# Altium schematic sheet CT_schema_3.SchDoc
size 511 x 403 mm
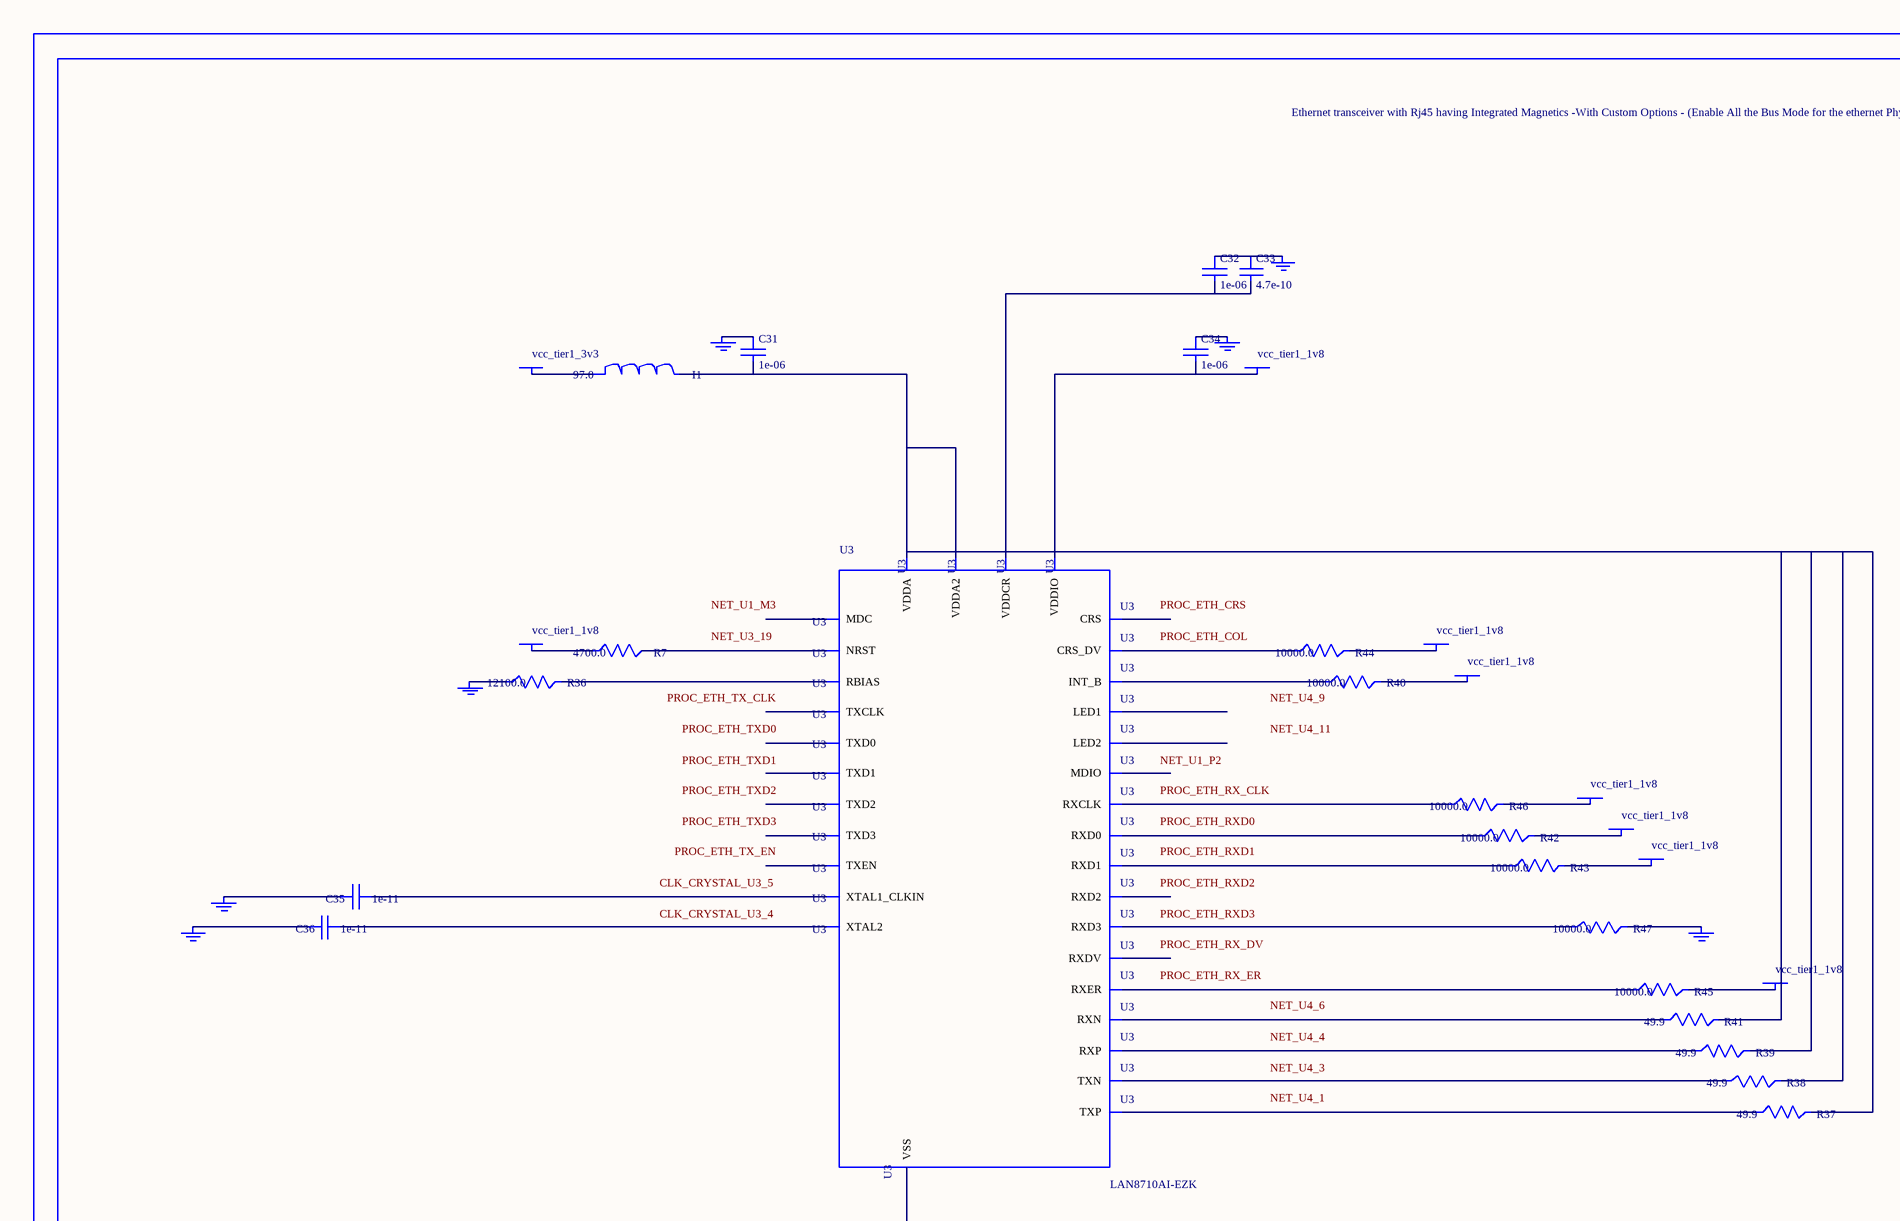
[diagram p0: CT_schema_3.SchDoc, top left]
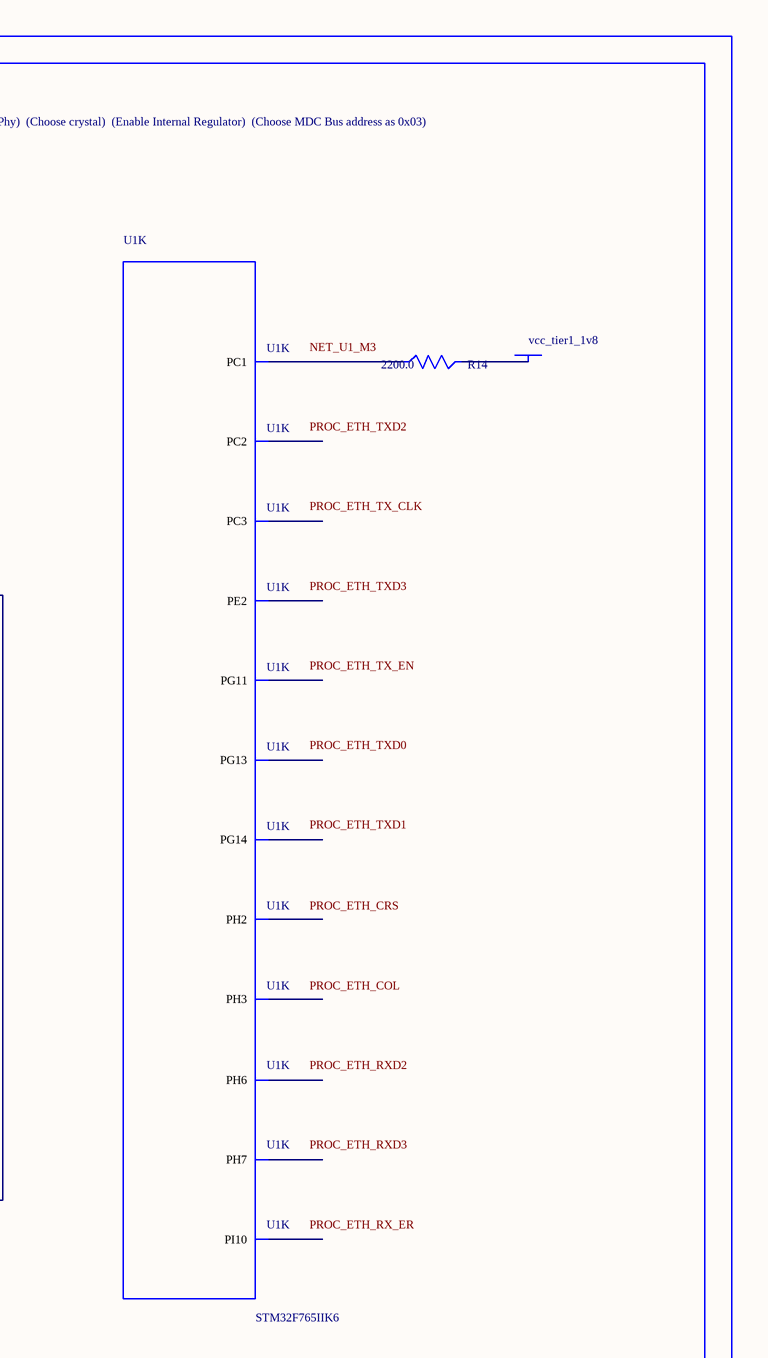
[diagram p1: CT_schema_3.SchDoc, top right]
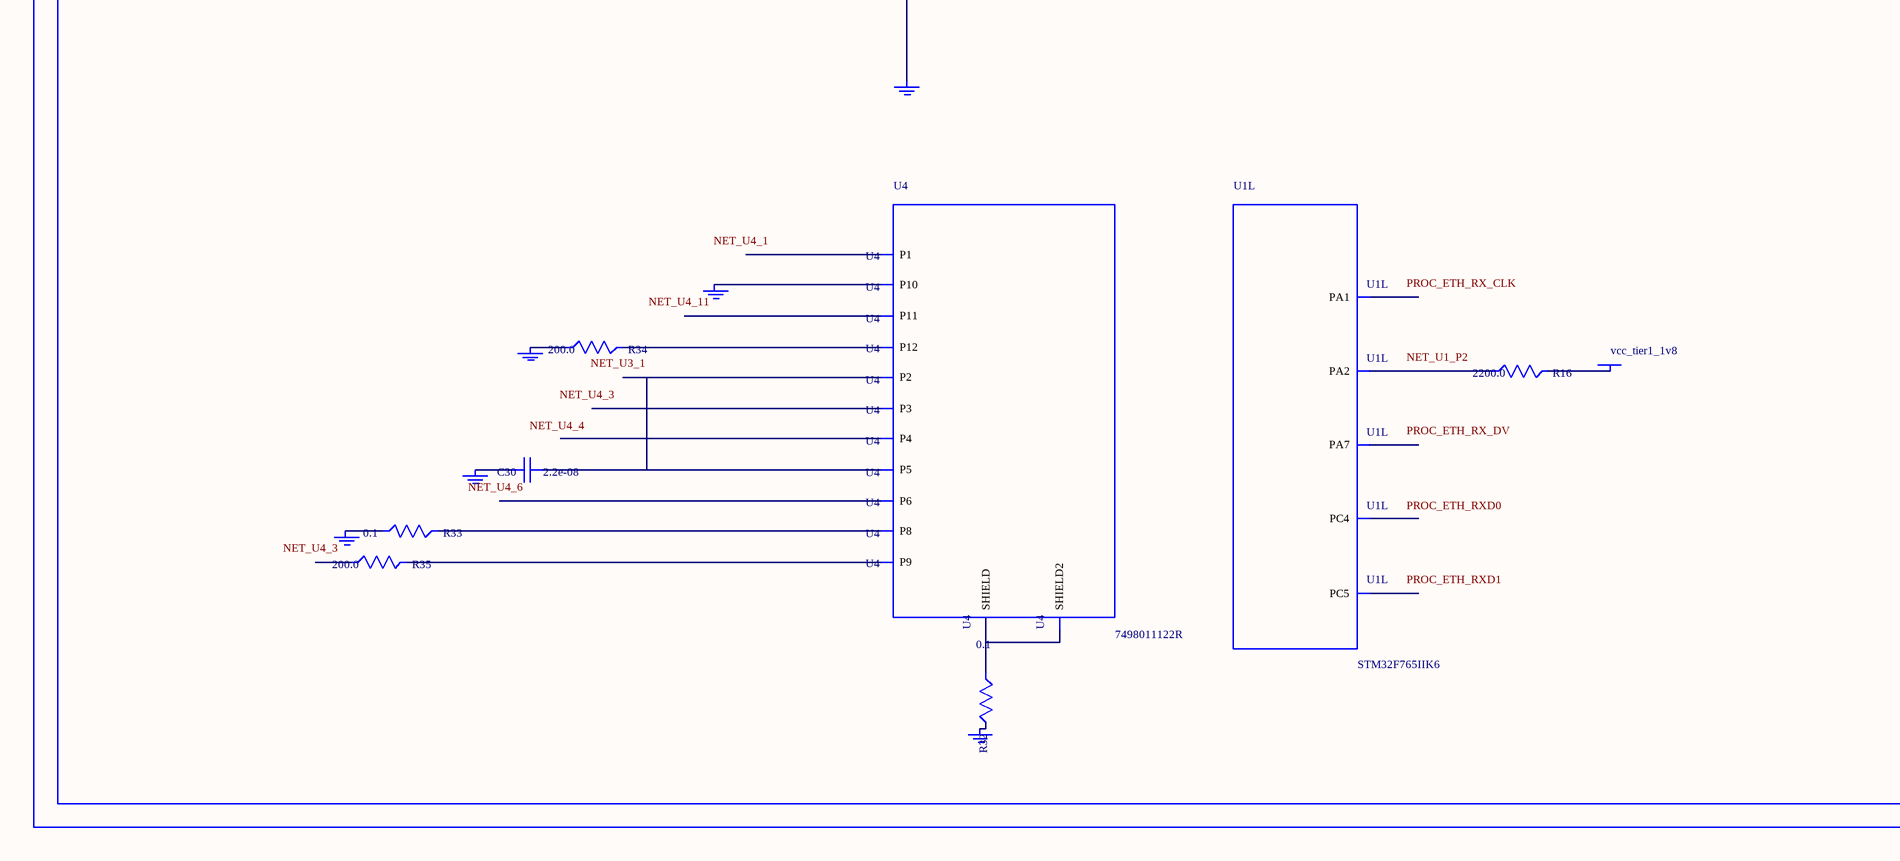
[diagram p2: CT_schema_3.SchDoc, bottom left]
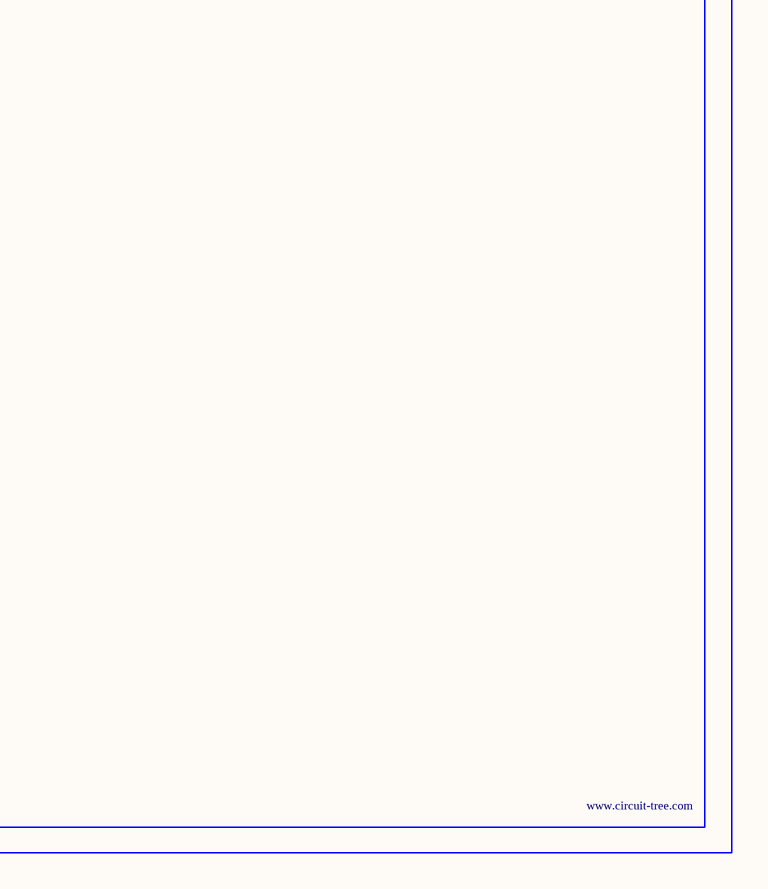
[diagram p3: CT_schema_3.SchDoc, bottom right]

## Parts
BORDER2  (no value)
C30  2.2e-08  [C0402]
C31  1e-06  [C0603]
C32  1e-06  [C0603]
C33  4.7e-10  [C0603]
C34  1e-06  [C0603]
C35  1e-11  [C0402]
C36  1e-11  [C0402]
GND_INSTANCE_2_0  (no value)
GND_INSTANCE_2_1  (no value)
GND_INSTANCE_2_2  (no value)
GND_INSTANCE_2_3  (no value)
GND_INSTANCE_2_4  (no value)
GND_INSTANCE_2_5  (no value)
GND_INSTANCE_2_6  (no value)
GND_INSTANCE_2_7  (no value)
GND_INSTANCE_2_8  (no value)
GND_INSTANCE_2_9  (no value)
GND_INSTANCE_2_10  (no value)
GND_INSTANCE_2_11  (no value)
GND_INSTANCE_2_12  (no value)
I1  97.0  [R0603]
POWER_INSTANCE_2_0  vcc_tier1_3v3
POWER_INSTANCE_2_1  vcc_tier1_1v8
POWER_INSTANCE_2_2  vcc_tier1_1v8
POWER_INSTANCE_2_3  vcc_tier1_1v8
POWER_INSTANCE_2_4  vcc_tier1_1v8
POWER_INSTANCE_2_5  vcc_tier1_1v8
POWER_INSTANCE_2_6  vcc_tier1_1v8
POWER_INSTANCE_2_7  vcc_tier1_1v8
POWER_INSTANCE_2_8  vcc_tier1_1v8
POWER_INSTANCE_2_9  vcc_tier1_1v8
POWER_INSTANCE_2_10  vcc_tier1_1v8
R7  4700.0  [R0603]
R14  2200.0  [R0603]
R16  2200.0  [R0603]
R32  0.1  [R0603]
R33  0.1  [R0603]
R34  200.0  [R0603]
R35  200.0  [R0603]
R36  12100.0  [R0603]
R37  49.9  [R0603]
R38  49.9  [R0603]
R39  49.9  [R0603]
R40  10000.0  [R0603]
R41  49.9  [R0603]
R42  10000.0  [R0603]
R43  10000.0  [R0603]
R44  10000.0  [R0603]
R45  10000.0  [R0603]
R46  10000.0  [R0603]
R47  10000.0  [R0603]
U1  STM32F765IIK6  [UFBGA176_25]  (parts K,L of 17)
U3  LAN8710AI-EZK  [QFN-32]
U4  7498011122R  [7498011122R]

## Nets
NetC30_1: C30.1 U4.2(P2) U4.5(P5)
NetC30_2: C30.2 GND_INSTANCE_2_8.0(GND)
NetC31_1: C31.1 GND_INSTANCE_2_0.0(GND)
NetC31_2: C31.2 I1.2 R37.2 R38.2 R39.2 R41.2 U3.1(VDDA) U3.27(VDDA2)
NetC32_1: C32.1 C33.1 GND_INSTANCE_2_3.0(GND)
NetC32_2: C32.2 C33.2 U3.6(VDDCR)
NetC34_1: C34.1 GND_INSTANCE_2_5.0(GND)
NetC34_2: C34.2 POWER_INSTANCE_2_4.0(PWR) U3.12(VDDIO)
NetC35_1: C35.1 U3.5(XTAL1_CLKIN)
NetC35_2: C35.2 GND_INSTANCE_2_2.0(GND)
NetC36_1: C36.1 U3.4(XTAL2)
NetC36_2: C36.2 GND_INSTANCE_2_1.0(GND)
NetGND_INSTANCE_2_4_0: GND_INSTANCE_2_4.0(GND) R47.2
NetGND_INSTANCE_2_6_0: GND_INSTANCE_2_6.0(GND) R36.1
NetGND_INSTANCE_2_7_0: GND_INSTANCE_2_7.0(GND) U3.EXP(VSS)
NetGND_INSTANCE_2_9_0: GND_INSTANCE_2_9.0(GND) R33.1
NetGND_INSTANCE_2_10_0: GND_INSTANCE_2_10.0(GND) U4.10(P10)
NetGND_INSTANCE_2_11_0: GND_INSTANCE_2_11.0(GND) R34.1
NetGND_INSTANCE_2_12_0: GND_INSTANCE_2_12.0(GND) R32.2
NetI1_1: I1.1 POWER_INSTANCE_2_0.0(PWR)
NetPOWER_INSTANCE_2_1_0: POWER_INSTANCE_2_1.0(PWR) R46.2
NetPOWER_INSTANCE_2_2_0: POWER_INSTANCE_2_2.0(PWR) R43.2
NetPOWER_INSTANCE_2_3_0: POWER_INSTANCE_2_3.0(PWR) R42.2
NetPOWER_INSTANCE_2_5_0: POWER_INSTANCE_2_5.0(PWR) R45.2
NetPOWER_INSTANCE_2_6_0: POWER_INSTANCE_2_6.0(PWR) R44.2
NetPOWER_INSTANCE_2_7_0: POWER_INSTANCE_2_7.0(PWR) R40.2
NetPOWER_INSTANCE_2_8_0: POWER_INSTANCE_2_8.0(PWR) R7.1
NetPOWER_INSTANCE_2_9_0: POWER_INSTANCE_2_9.0(PWR) R14.2
NetPOWER_INSTANCE_2_10_0: POWER_INSTANCE_2_10.0(PWR) R16.2
NetR7_2: R7.2 U3.19(NRST)
NetR14_1: R14.1 U1.M3(PC1)
NetR16_1: R16.1 U1.P2(PA2)
NetR32_1: R32.1 U4.13(SHIELD) U4.14(SHIELD2)
NetR33_2: R33.2 U4.8(P8)
NetR34_2: R34.2 U4.12(P12)
NetR35_2: R35.2 U4.9(P9)
NetR36_2: R36.2 U3.32(RBIAS)
NetR37_1: R37.1 U3.29(TXP)
NetR38_1: R38.1 U3.28(TXN)
NetR39_1: R39.1 U3.31(RXP)
NetR40_1: R40.1 U3.18(INT_B)
NetR41_1: R41.1 U3.30(RXN)
NetR42_1: R42.1 U3.11(RXD0)
NetR43_1: R43.1 U3.10(RXD1)
NetR44_1: R44.1 U3.15(CRS_DV)
NetR45_1: R45.1 U3.13(RXER)
NetR46_1: R46.1 U3.7(RXCLK)
NetR47_1: R47.1 U3.8(RXD3)

Not connected (* = marked no-connect by the designer): R35 1; U1 A2(PE2) A7(PG14) A8(PG13) B9(PG11) E3(PI10) F4(PH2) G4(PH3) M4(PC2) M5(PC3) M11(PH6) N2(PA1) N5(PC4) N12(PH7) P5(PC5) R3(PA7); U3 2(LED2) 3(LED1) 9(RXD2) 14(CRS) 16(MDIO) 17(MDC) 20(TXCLK) 21(TXEN) 22(TXD0) 23(TXD1) 24(TXD2) 25(TXD3) 26(RXDV); U4 1(P1) 3(P3) 4(P4) 6(P6) 11(P11)

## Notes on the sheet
- Labels drawn without touching a wire or pin: CLK_CRYSTAL_U3_4, CLK_CRYSTAL_U3_5, NET_U1_M3, NET_U1_P2, NET_U3_1, NET_U3_19, NET_U4_1, NET_U4_3, NET_U4_4, NET_U4_6, NET_U4_9, NET_U4_11, PROC_ETH_COL, PROC_ETH_CRS, PROC_ETH_RX_CLK, PROC_ETH_RX_DV, PROC_ETH_RX_ER, PROC_ETH_RXD0, PROC_ETH_RXD1, PROC_ETH_RXD2, PROC_ETH_RXD3, PROC_ETH_TX_CLK, PROC_ETH_TX_EN, PROC_ETH_TXD0, PROC_ETH_TXD1, PROC_ETH_TXD2, PROC_ETH_TXD3

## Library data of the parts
BORDER2 = BORDER_PAGE2
C30 = C0402C223K3RAC
C31 C32 C34 = C0603C105K3RACTU
C33 = 06031C471KAZ2A
C35 C36 = C0402C100K3GACTU
GND_INSTANCE_2_0-GND_INSTANCE_2_12 = GND
I1 = I1
POWER_INSTANCE_2_0-POWER_INSTANCE_2_10 = PWR
R7 = RC0603JR-074K7L
R14 R16 = RC0603JR-072K2L
R32 R33 = ERJ-3RSFR10V
R34 R35 = RC0603JR-07200RL
R36 = TNPW060312K1BEEA
R37-R39 R41 = RC0603FR-0749R9L
R40 R42-R47 = RC0603JR-0710KL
